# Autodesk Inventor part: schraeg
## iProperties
Shininess: 64.0
Length Units: 11269
Angle Units: 11279
Time Units: 11290
Mass Units: 11283
Length Display Precision: 3
Angle Display Precision: 2
Compacted: True
Part Number: schraeg
Document SubType Name: Modeling
Created: 2003-08
Material: Standard
Cost Center: 0.129 kg
Authority: 129376.5 mm^3
Designer: juergen
Density: 0.0
Volumn: 0.0
Area: 0.0
PropertySet Name: Model Information
Control State: 0
Master: False
Checked Out: False
SaveDate: 2003-08-05
SaveTime: 11:05
TotalMass: 0.129 kg
TotalVolume: 129376.5 mm^3
Author: juergen
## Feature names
1. Extrusion1
2. 1. Extriusion mit winkel [Extrusion]
3. 2. erhebung
4. Sweeping1
